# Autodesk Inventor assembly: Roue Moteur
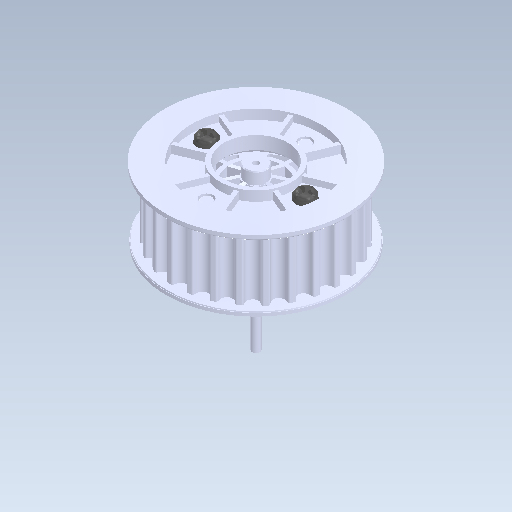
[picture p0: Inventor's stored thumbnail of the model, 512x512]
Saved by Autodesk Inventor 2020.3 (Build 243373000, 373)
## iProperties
Created: 2018-09
Part Number: Roue Moteur
Document SubType Name: Assembly
Designer: ficho
Mass: 11.7501 g
Surface Area: 168.738 cm^2
Volume: 11.7501 cm^3
Density: 1 g/cm^3
Sending System: SolidWorks 2015
Last Author: adrien
Last Saved: 2019-01-14
Author: ficho
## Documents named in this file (5)
- D:\travail\année 2020-2021\2I2D\laveur de vitre\Lave vitre\4 Dossier Ressources\1 Modèles 3D Solidworks\Roue Moteur.iam
- D:\travail\année 2020-2021\2I2D\laveur de vitre\Lave vitre\4 Dossier Ressources\1 Modèles 3D Solidworks\Vis 3x8.ipt
- D:\travail\année 2020-2021\2I2D\laveur de vitre\Lave vitre\4 Dossier Ressources\1 Modèles 3D Solidworks\Roue chenille entrainement.ipt
- D:\travail\année 2020-2021\2I2D\laveur de vitre\Lave vitre\4 Dossier Ressources\1 Modèles 3D Solidworks\Flasque roue chenille.ipt
- D:\travail\année 2020-2021\2I2D\laveur de vitre\Lave vitre\4 Dossier Ressources\1 Modèles 3D Solidworks\Porte satélites.ipt
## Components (5 placed, 4 different names)
1. Vis 3x8:1
2. Vis 3x8:2
3. Roue chenille entrainement:1 — Placage:1, Placage:2, Placage:3
4. Flasque roue chenille:1
5. Porte satélites:1 — Placage:1, Placage:2, Placage:3
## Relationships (3: Mate 3)
- Placage:1 [Mate]: Roue chenille entrainement:1 ↔ Porte satélites:1
- Placage:2 [Mate]: Roue chenille entrainement:1 ↔ Porte satélites:1
- Placage:3 [Mate]: Roue chenille entrainement:1 ↔ Porte satélites:1
